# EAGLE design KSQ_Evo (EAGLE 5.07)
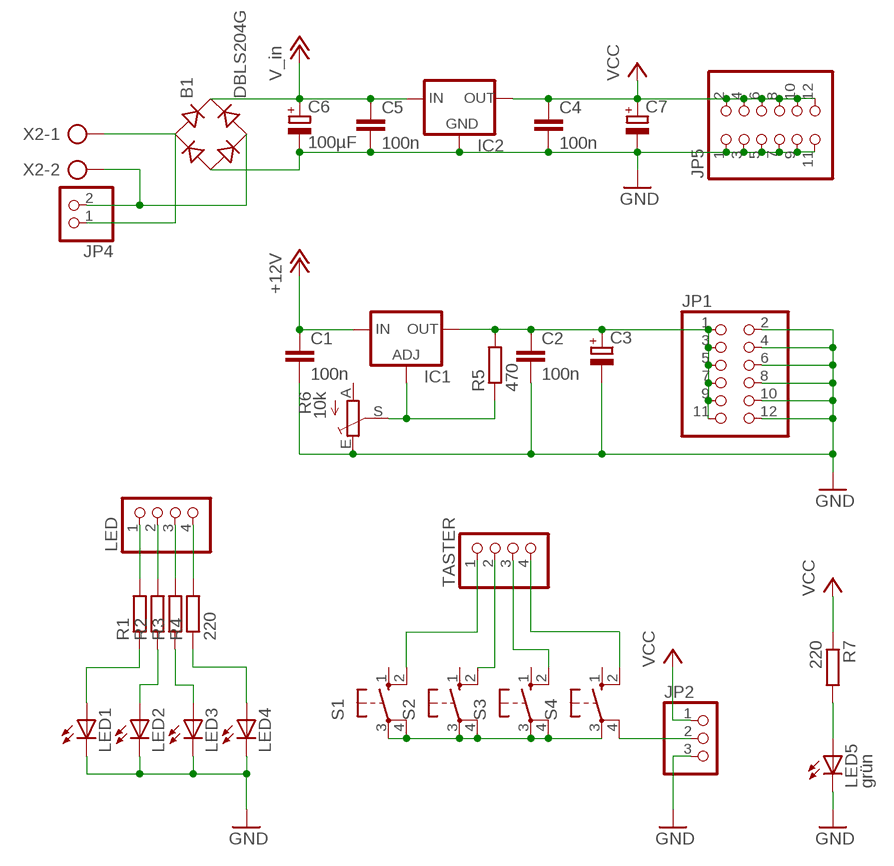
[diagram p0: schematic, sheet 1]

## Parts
B1  DBLS204G  [DBS]
C1  100n  C-EUC1206  [C1206]
C2  100n  C-EUC1206  [C1206]
C3  CPOL-EUE2-4  [E2-4]
C4  100n  C-EUC1206  [C1206]
C5  100n  C-EUC1206  [C1206]
C6  100µF  CPOL-EUE2.5-6  [E2,5-6]
C7  CPOL-EUE2-4  [E2-4]
IC1  LM317TS  [317TS]
IC2  78XXS  [78XXS]
JP1  PINHD-2X6  [2X06]
JP2  PINHD-1X3  [1X03]
JP4  PINHD-1X2  [1X02]
JP5  PINHD-2X6  [2X06]
LED  PINHD-1X4  [1X04]
LED1  LED3MM  [LED3MM]
LED2  LED3MM  [LED3MM]
LED3  LED3MM  [LED3MM]
LED4  LED3MM  [LED3MM]
LED5  grün  LED3MM  [LED3MM]
R1  R-EU_R0805  [R0805]
R2  R-EU_R0805  [R0805]
R3  R-EU_R0805  [R0805]
R4  220  R-EU_R0805  [R0805]
R5  470  R-EU_R0805  [R0805]
R6  10k  TRIM_EU-PT10  [PT-10]
R7  220  R-EU_R0805  [R0805]
S1  10-XX  [B3F-10XX]
S2  10-XX  [B3F-10XX]
S3  10-XX  [B3F-10XX]
S4  10-XX  [B3F-10XX]
TASTER  PINHD-1X4  [1X04]
X2  AK500/2  [AK500/2]

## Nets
+12V: B1.+ C1.1 C5.1 C6.+ IC1.3(IN) IC2.IN ; supply symbol labelled V_in
GND: B1.- C1.2 C2.2 C3.- C4.2 C5.2 C6.- C7.- IC2.GND JP1.2 JP1.4 JP1.6 JP1.8 JP1.10 JP1.12 JP2.3 JP5.1 JP5.3 JP5.5 JP5.7 JP5.9 JP5.11 LED1.K(C) LED2.K(C) LED3.K(C) LED4.K(C) LED5.K(C) R6.E
N$1: LED.1 R1.2
N$2: LED.2 R2.2
N$3: B1.AC2 JP4.2 X2.2
N$4: LED5.A R7.2
N$5: LED.3 R3.2
N$6: LED.4 R4.2
N$7: LED2.A R2.1
N$8: LED3.A R3.1
N$9: LED1.A R1.1
N$10: LED4.A R4.1
N$11: S3.2(S1) TASTER.3
N$12: S2.2(S1) TASTER.2
N$13: JP2.2 S4.4(P1)
N$14: S1.2(S1) TASTER.1
N$15: S4.2(S1) TASTER.4
N$16: S1.3(P) S1.4(P1) S2.3(P) S2.4(P1) S3.3(P) S3.4(P1) S4.3(P)
N$17: C2.1 C3.+ IC1.2(OUT) JP1.1 JP1.3 JP1.5 JP1.7 JP1.9 JP1.11 R5.2
N$19: IC1.1(ADJ) R5.1 R6.S
N$20: B1.AC1 JP4.1 X2.1
VCC: C4.1 C7.+ IC2.OUT JP2.1 JP5.2 JP5.4 JP5.6 JP5.8 JP5.10 JP5.12 R7.1
Unconnected: R6.A S1.1(S) S2.1(S) S3.1(S) S4.1(S)

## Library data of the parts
B1 = rectifier:DB?*G: Single Phase 1.0 AMP Glass Passivated Bridge Rectifier Taiwan Semiconductor Co.,Ltd. - TSC Source: http://www.taiwansemi.com/TSCbig5/ezcatfiles/cust/img/img/db101g.pdf http://www.ts.com.tw/db/pictures/modules/PDT/PDT060207001/DBLS201G.pdf
C1 C2 C4 C5 = rcl:C-EU: CAPACITOR, European symbol
C3 C6 C7 = rcl:CPOL-EU: POLARIZED CAPACITOR, European symbol
IC1 = v-reg:LM317TS: VOLTAGE REGULATOR
IC2 = v-reg:78XXS: VOLTAGE REGULATOR
JP1 JP5 = pinhead:PINHD-2X6: PIN HEADER
JP2 = pinhead:PINHD-1X3: PIN HEADER
JP4 = pinhead:PINHD-1X2: PIN HEADER
LED TASTER = pinhead:PINHD-1X4: PIN HEADER
LED1-LED5 = led:LED: LED
R1-R5 R7 = rcl:R-EU_: RESISTOR, European symbol
R6 = pot:TRIM_EU-: POTENTIOMETER
S1-S4 = switch-omron:10-XX: OMRON SWITCH
X2 = con-ptr500:AK500/2: CONNECTOR

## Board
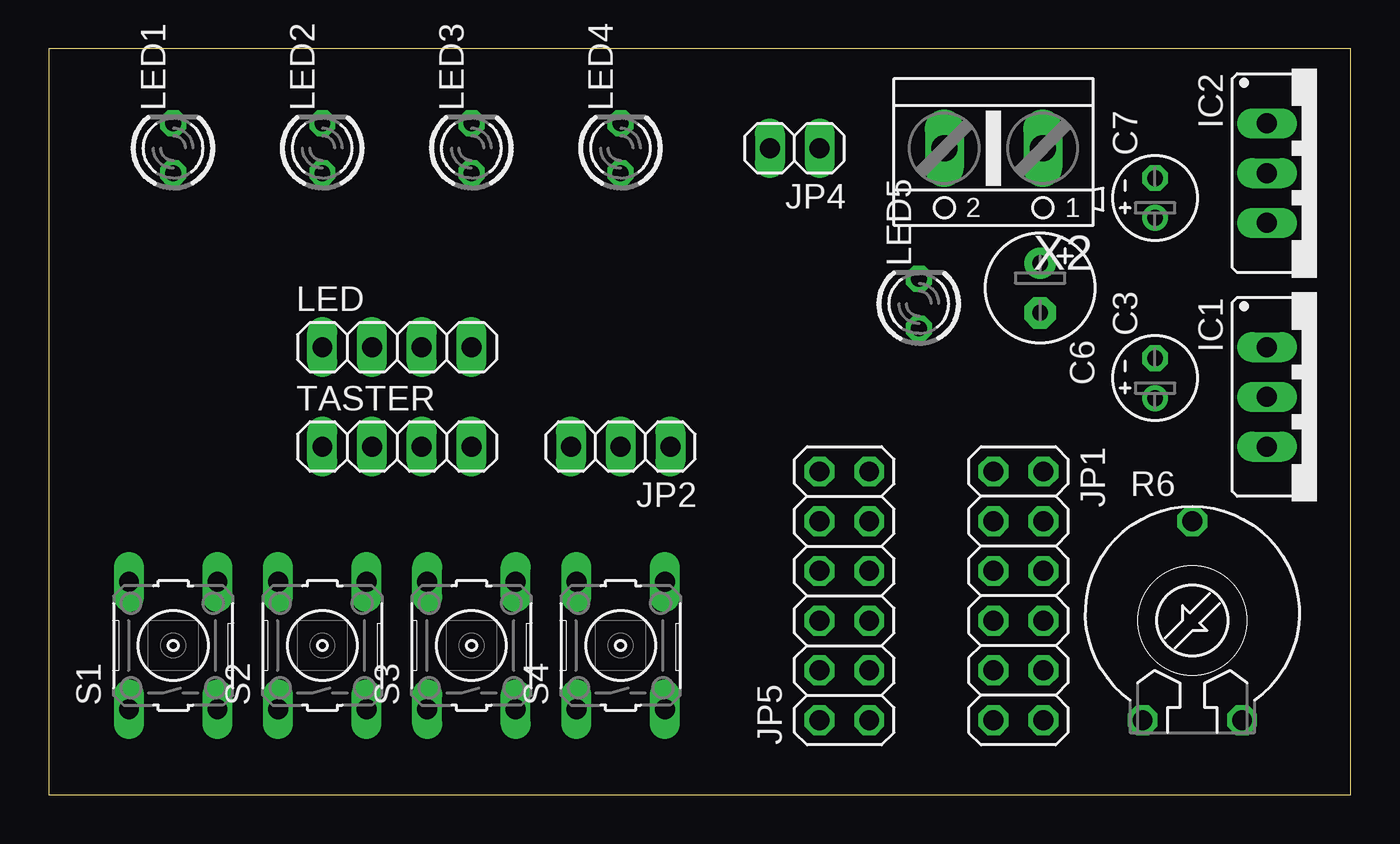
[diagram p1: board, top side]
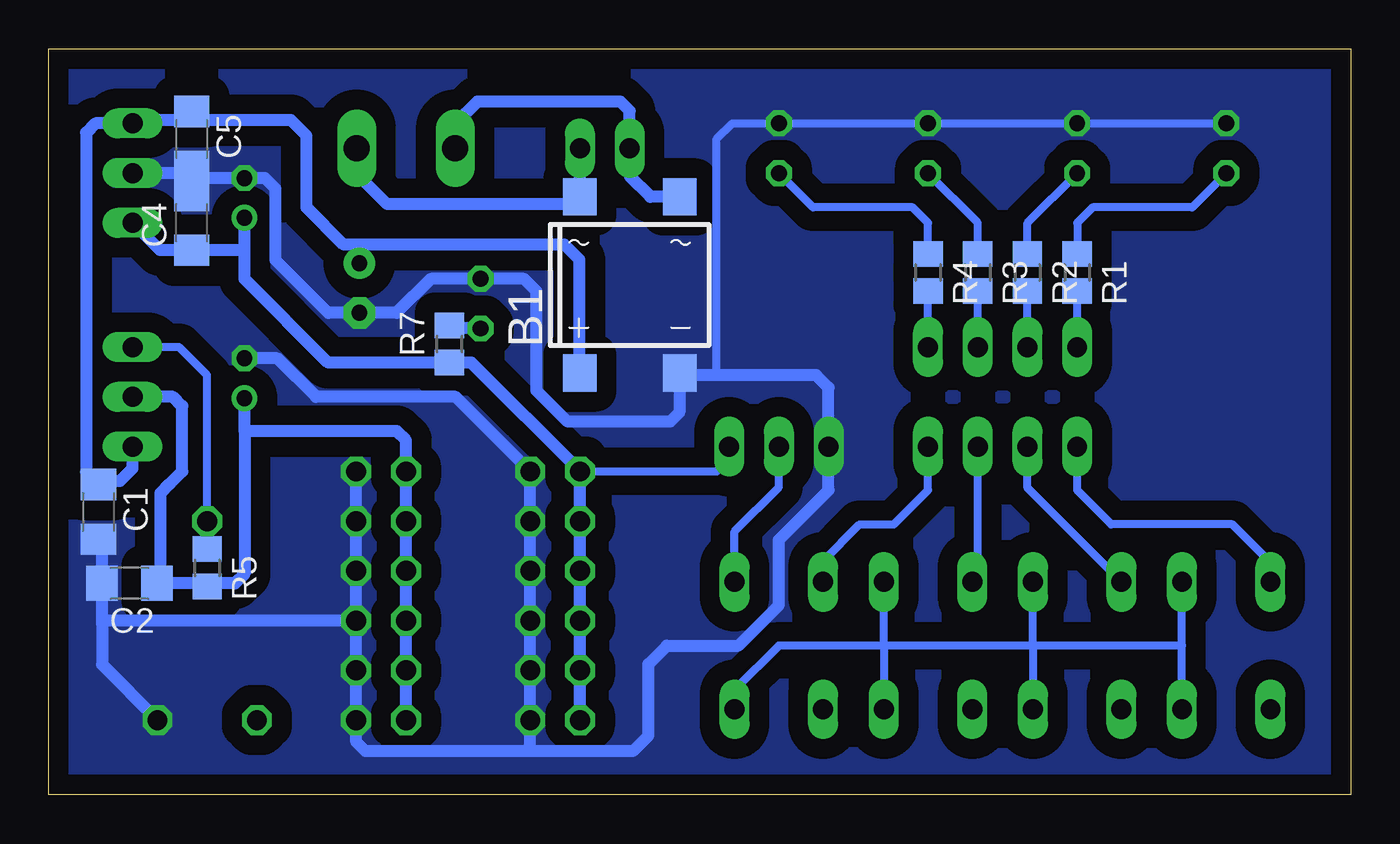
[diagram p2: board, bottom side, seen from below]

Size 66.5 x 38.09 mm. Coordinates in mm from the lower left corner, seen from the top.
Outline: 0,0 66.5,0 66.5,38.09 0,38.09 0,0
Copper layers (1*16): Top 0.035mm / dielectric 1.5mm / Bottom 0.035mm
Design rules "default": minimum track width 10mil, minimum drill 24mil, track to track 8mil, track to pad 8mil, pad to pad 8mil, via to via 8mil, smd to smd 8mil, copper to edge 40mil, drill to drill 8mil, minimum pad ring 10mil, minimum via ring 8mil, stop-mask expansion 4mil, vias tented up to drill 0mil, thermal gap 10mil

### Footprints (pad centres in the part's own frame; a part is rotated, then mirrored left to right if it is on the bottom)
DBS = smd 1.7 x 1.9: + -2.55,-4.5; - 2.55,-4.5; AC1 -2.55,4.5; AC2 2.55,4.5
C1206 = smd 1.6 x 1.8: 1 -1.4,0; 2 1.4,0
E2-4 = drill 0.813 pad 1.27 round: + -1.016,0 | drill 0.813 pad 1.27 octagon: - 1.016,0
E2,5-6 = drill 0.813 pad 1.6 round: + -1.27,0 | drill 0.813 pad 1.6 octagon: - 1.27,0
317TS = drill 1.016 long: 1 -2.54,-2.54; 2 0,-2.54; 3 2.54,-2.54
78XXS = drill 1.016 long: GND 0,-2.54; IN -2.54,-2.54; OUT 2.54,-2.54
2X06 = drill 1.016 octagon: 1 -6.35,-1.27; 2 -6.35,1.27; 3 -3.81,-1.27; 4 -3.81,1.27; 5 -1.27,-1.27; 6 -1.27,1.27; 7 1.27,-1.27; 8 1.27,1.27; 9 3.81,-1.27; 10 3.81,1.27; 11 6.35,-1.27; 12 6.35,1.27
1X03 = drill 1.016 long: 1 -2.54,0; 2 0,0; 3 2.54,0
1X02 = drill 1.016 long: 1 -1.27,0; 2 1.27,0
1X04 = drill 1.016 long: 1 -3.81,0; 2 -1.27,0; 3 1.27,0; 4 3.81,0
LED3MM = drill 0.813 octagon: A -1.27,0; K 1.27,0
R0805 = smd 1.3 x 1.5: 1 -0.95,0; 2 0.95,0
PT-10 = drill 1.016 octagon: A -2.54,-5.08; E 2.54,-5.08; S 0,5.08
B3F-10XX = drill 1.016 long: 1 -3.251,2.261; 2 3.251,2.261; 3 -3.251,-2.261; 4 3.251,-2.261
AK500/2 = drill 1.321 long: 1 -2.515,0; 2 2.515,0

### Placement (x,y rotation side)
B1  36.83,26.04 0 bottom
C1  63.98,14.45 270 bottom
C2  62.39,10.8 180 bottom
C3  56.52,21.27 90 top
C4  59.21,29.21 90 bottom
C5  59.21,33.5 270 bottom
C6  50.64,25.88 270 top
C7  56.52,30.48 90 top
IC1  64.77,20.32 270 top
IC2  64.77,31.75 270 top
JP1  49.53,10.16 270 top
JP2  29.21,17.78 180 top
JP4  38.1,33.02 180 top
JP5  40.64,10.16 90 top
LED  17.78,22.86 0 top
LED1  6.35,33.02 90 top
LED2  13.97,33.02 90 top
LED3  21.59,33.02 90 top
LED4  29.21,33.02 90 top
LED5  44.45,25.08 90 top
R1  13.97,26.67 270 bottom
R2  16.51,26.67 270 bottom
R3  19.05,26.67 270 bottom
R4  21.59,26.67 270 bottom
R5  58.42,11.59 270 bottom
R6  58.42,8.89 0 top
R7  46.04,23.02 90 bottom
S1  6.35,7.62 90 top
S2  13.97,7.62 90 top
S3  21.59,7.62 90 top
S4  29.21,7.62 90 top
TASTER  17.78,17.78 0 top
X2  48.26,33.02 180 top

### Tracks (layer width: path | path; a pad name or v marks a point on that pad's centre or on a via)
+12V
  Bottom 0.61: 50.8,28.1 40.16,28.1 39.4,27.34 39.4,21.08 B1.+ | 50.8,28.1 51.44,28.1 53.34,30 53.34,33.66 54.13,34.45 59.05,34.45 | 59.05,34.45 62.07,34.45 IC2.IN 64.14,34.29 64.61,33.81 64.61,16.48 C1.1 63.79,16.03 62.87,16.03 62.23,16.67 IC1.3 | C5.1 59.21,34.61 59.05,34.45 | C6.+ 50.64,27.94 50.8,28.1
GND
  Bottom 0.406: LED1.K LED2.K LED3.K LED4.K 31.59,34.29 32.38,33.5 32.38,21.59 32.23,21.43
  Bottom 0.61: C6.- 48.74,24.61 46.99,26.35 LED5.K 42.23,26.35 41.59,25.72 41.59,20.64 40.01,19.05 34.77,19.05 34.29,19.53 34.29,21.52 B1.- 34.18,21.43 32.23,21.43 27.3,21.43 26.67,20.8 JP2.3 26.67,15.56 29.21,13.02 29.21,9.68 31.27,7.62 34.92,7.62 35.88,6.67 35.88,3.02 36.67,2.22 41.75,2.22 | C6.- 52.23,24.61 54.93,27.3 54.93,30.96 55.47,31.5 C7.- 58.61,31.5 58.87,31.75 | C6.- | 58.87,31.75 C5.2 | 58.87,31.75 IC2.GND | C5.2 C4.2 | C5.2 | 41.75,2.22 50.32,2.22 50.8,2.7 JP1.12 JP1.10 JP1.8 | C3.- 54.83,22.29 52.86,20.32 45.72,20.32 JP5.11 JP5.9 JP5.7 JP5.5 JP5.3 JP5.1 41.91,2.38 41.75,2.22 | JP1.2 JP1.4 JP1.6 JP1.8 | 63.79,8.73 63.79,6.64 R6.E | 63.79,8.73 C2.2 63.79,12.86 C1.2 | JP1.8 63.63,8.89 63.79,8.73
  pour Bottom (isolate 1.016, no thermals): -0.48,38.58 66.99,38.58 66.99,-0.48 -0.48,-0.48
N$1
  Bottom 0.406: LED.1 R1.2
N$2
  Bottom 0.406: LED.2 R2.2
N$3
  Bottom 0.61: X2.2 45.74,34.27 44.61,35.4 37.31,35.4 36.83,34.92 JP4.2 36.83,31.59 35.77,30.54 B1.AC2
N$4
  Bottom 0.61: LED5.A 45.88,23.81 R7.2
N$5
  Bottom 0.406: LED.3 R3.2
N$6
  Bottom 0.406: LED.4 R4.2
N$7
  Bottom 0.406: R2.1 16.51,29.21 LED2.A
N$8
  Bottom 0.406: R3.1 19.05,29.21 LED3.A
N$9
  Bottom 0.406: R1.1 13.97,29.21 13.18,30 8.1,30 LED1.A
N$10
  Bottom 0.406: R4.1 21.59,29.21 22.38,30 27.46,30 LED4.A
N$11
  Bottom 0.406: TASTER.3 19.05,11.15 S3.2
N$12
  Bottom 0.406: TASTER.2 16.51,15.67 S2.2
N$13
  Bottom 0.406: S4.4 31.47,13.46 29.21,15.72 JP2.2
N$14
  Bottom 0.406: TASTER.1 13.97,15.56 12.22,13.81 6.03,13.81 4.13,11.91 4.13,10.91 S1.2
N$15
  Bottom 0.406: TASTER.4 21.59,15.56 23.34,13.81 25.08,13.81 26.99,11.91 26.99,10.91 S4.2
N$16
  Bottom 0.406: 16.23,7.62 S2.3 | 23.85,7.62 S3.3 | 16.23,7.62 S2.4 | 16.23,7.62 23.85,7.62 | S3.4 23.85,8.1 23.85,7.62 | S1.3 8.61,7.62 | 8.61,7.62 S1.4 | 8.61,7.62 16.23,7.62 | S4.3 31.47,5.36 29.21,7.62 23.85,7.62
N$17
  Bottom 0.61: JP1.11 JP1.9 JP1.7 JP1.5 JP1.3 JP1.1 48.26,18.1 48.74,18.57 56.52,18.57 | IC1.2 60.17,20.32 59.69,19.84 59.69,16.51 60.33,15.88 | 60.33,15.88 | 60.33,15.88 60.8,15.4 60.8,10.82 60.83,10.79 C2.1 | 56.52,18.57 56.52,11.27 56.99,10.79 58.26,10.79 | 56.52,18.57 C3.+ | 58.26,10.79 C2.1 | C2.1 | R5.2 58.26,10.79
N$19
  Bottom 0.406: IC1.1 59.85,22.86 58.42,21.43 R6.S
  Bottom 0.61: R5.1 R6.S
N$20
  Bottom 0.61: X2.1 50.77,31.73 49.21,30.16 39.48,30.16 B1.AC1 39.37,30.07 JP4.1
VCC
  Bottom 0.406: JP5.12 32.38,16.51 31.75,17.14 JP2.1
  Bottom 0.61: 56.52,27.78 56.52,26.35 52.23,22.07 45.88,22.07 | 56.52,27.78 C7.+ | 45.88,22.07 44.93,22.07 JP5.12 JP5.10 JP5.8 JP5.6 JP5.4 JP5.2 | R7.1 45.88,22.07 | IC2.OUT 60.83,27.81 C4.1 56.54,27.81 56.52,27.78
